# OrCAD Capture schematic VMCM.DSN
size A
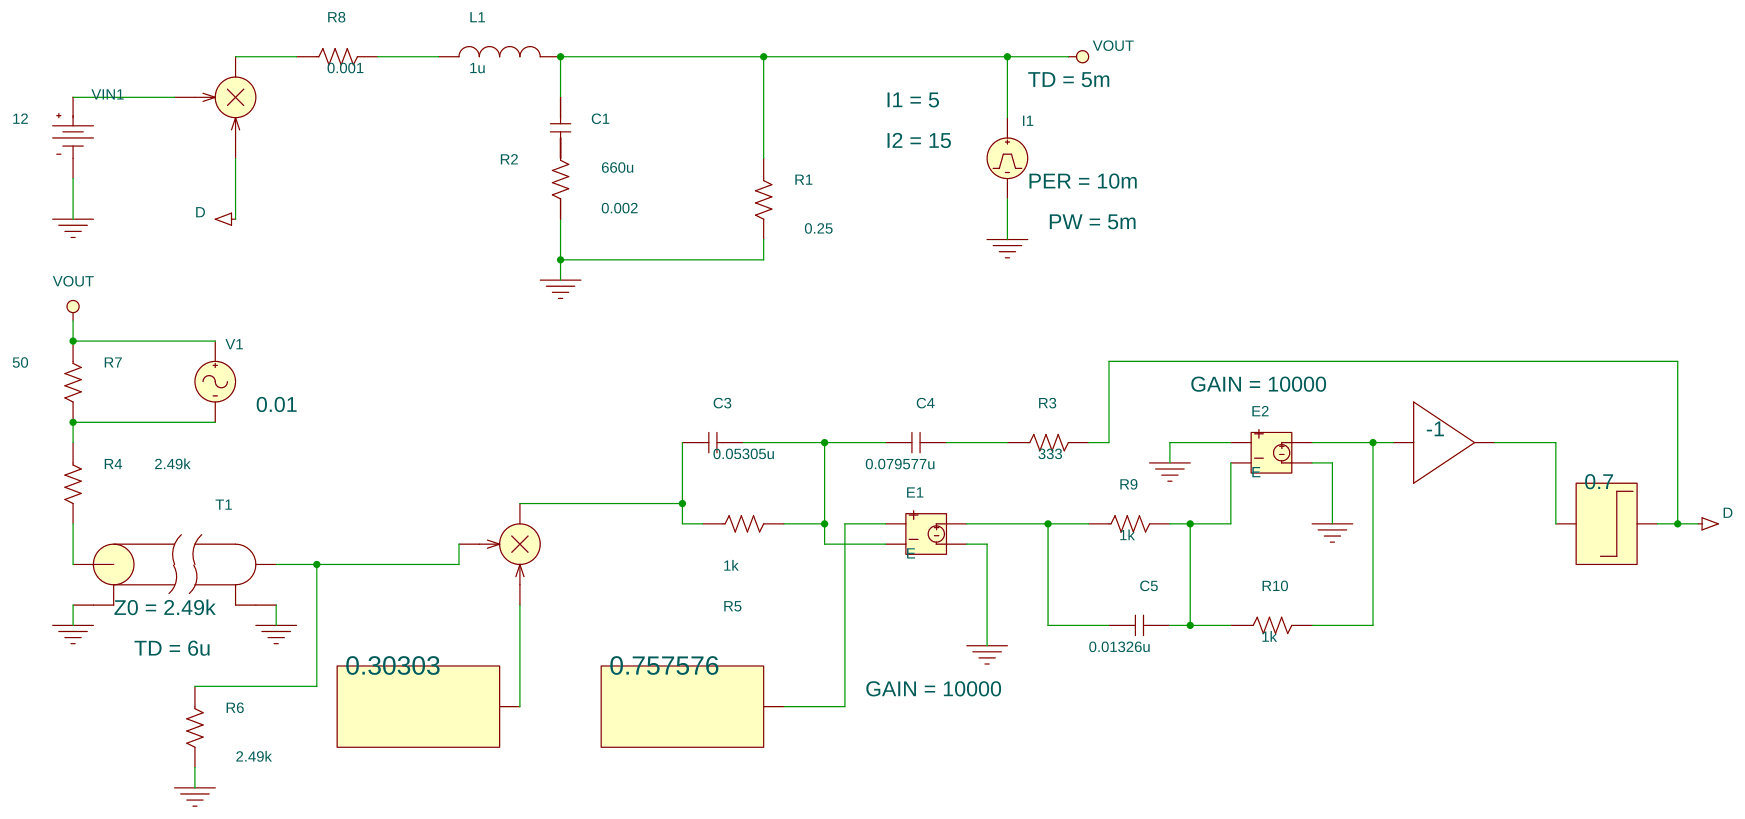
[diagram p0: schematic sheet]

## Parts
ABM1  ABM
ABM2  ABM
C1  660u  [CK05]
C3  0.05305u  [CK05]
C4  0.079577u  [CK05]
C5  0.01326u  [CK05]
E1  E
E2  E
GAIN1  GAIN
I1  IPULSE
L1  1u  [L2012C]
LIMIT1  LIMIT
MULT1  MULT
MULT2  MULT
R1  0.25  [RC05]
R2  0.002  [RC05]
R3  333  [RC05]
R4  2.49k  [RC05]
R5  1k  [RC05]
R6  2.49k  [RC05]
R7  50  [RC05]
R8  0.001  [RC05]
R9  1k  [RC05]
R10  1k  [RC05]
T1  T
V1  VAC
VIN1  VDC

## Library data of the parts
ABM1 = ABM: EXP1: 0.30303
ABM2 = ABM: EXP1: 0.757576
C1 C3-C5 = C
E1 E2 = E: GAIN: 10000
GAIN1 = GAIN: GAIN: -1
I1 = IPULSE: I1: 5; I2: 15; PER: 10m; PW: 5m; TD: 5m; TF: 50u; TR: 50u
L1 = L
LIMIT1 = LIMIT: HI: 0.7
MULT1 MULT2 = MULT
R1-R10 = R
T1 = T: TD: 6u; Z0: 2.49k
V1 = VAC: ACMAG: 0.01
VIN1 = VDC: DC: 12

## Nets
0: E1.4 E2.1 E2.4 I1.2(-) R1.2 R2.2 R6.2 T1.2(A-) T1.4(B-) VIN1.1(-)
D: LIMIT1.2(OUT) MULT1.3(IN2) R3.2
Vout: C1.1 I1.1(+) L1.2 R1.1 R7.1 V1.1(+)
N00062: C1.2 R2.1
N00146: MULT1.1(IN1) VIN1.0(+)
N00330: ABM1.2(OUT) MULT2.3(IN2)
N00382: ABM2.2(OUT) E1.1
N00389: C3.2 C4.1 E1.2 R5.2
N00435: C3.1 MULT2.5(OUT) R5.1
N00451: C4.2 R3.1
N01054: R4.1 R7.2 V1.2(-)
N01892: MULT1.5(OUT) R8.1
N01895: L1.1 R8.2
N02390: MULT2.1(IN1) R6.1 T1.3(B+)
N02402: R4.2 T1.1(A+)
N02957: C5.1 E1.3 R9.1
N02983: C5.2 E2.2 R9.2 R10.1
N03008: E2.3 GAIN1.1(IN) R10.2
N03071: GAIN1.2(OUT) LIMIT1.1(IN)
